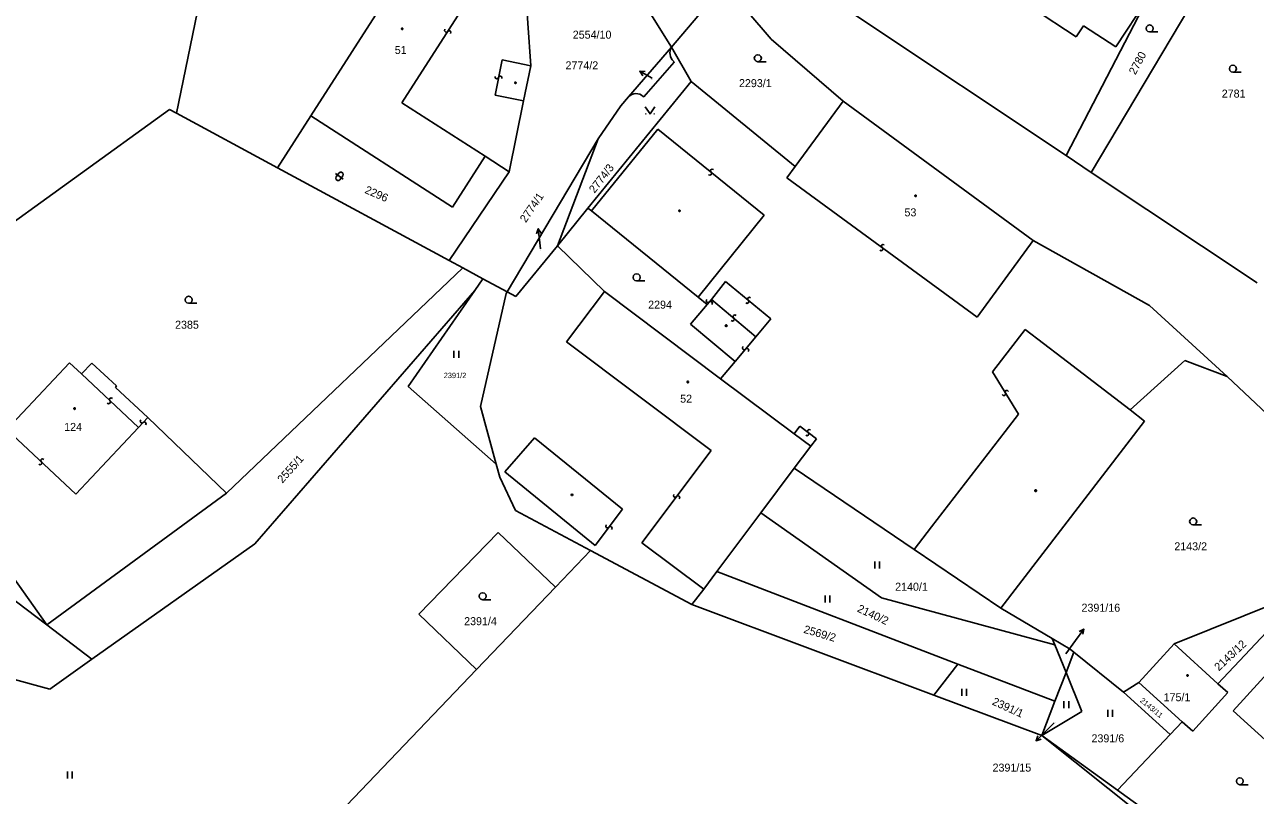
# Model space of a CAD drawing. Extents: x -747792 to -745414, y -1093712 to -1091463.
# Drawn here: x -746752.4 to -746621.6, y -1093197 to -1093115.1 of the extents above; entities that cross this region are included whole.
import ezdxf

# ---------------------------------------------------------------- set-up
doc = ezdxf.new("R2010")
doc.units = 0
for name, color, linetype in [('Pracovní_bod JDTM STC_VC', 7, 'Continuous'), ('Pracovní_bod JDTM STC_VC - výška', 7, 'Continuous'), ('Pracovní_bod JDTM STC_VC - číslo', 7, 'Continuous'), ('Pracovní_bod NN - výška', 7, 'Continuous'), ('Pracovní_bod polohopisu', 7, 'Continuous'), ('Pracovní_bod polohopisu - výška', 7, 'Continuous')]:
    doc.layers.add(name, color=color, linetype=linetype)

msp = doc.modelspace()

# ---------------------------------------------------------------- linework, layer by layer
at = {"layer": 'Pracovní_bod JDTM STC_VC - výška'}
for points in [[(-746712.23, -1093115.44), (-746712.18, -1093115.45), (-746712.16, -1093115.49), (-746712.15, -1093115.52), (-746712.16, -1093115.56), (-746712.2, -1093115.6), (-746712.23, -1093115.6), (-746712.27, -1093115.59), (-746712.3, -1093115.56), (-746712.32, -1093115.52), (-746712.3, -1093115.48), (-746712.26, -1093115.44)], [(-746700.16, -1093121.19), (-746700.11, -1093121.26), (-746700.16, -1093121.33), (-746700.24, -1093121.33), (-746700.29, -1093121.26), (-746700.24, -1093121.19)], [(-746657.7, -1093133.19), (-746657.65, -1093133.2), (-746657.62, -1093133.24), (-746657.61, -1093133.27), (-746657.62, -1093133.31), (-746657.67, -1093133.35), (-746657.7, -1093133.35), (-746657.74, -1093133.34), (-746657.77, -1093133.31), (-746657.78, -1093133.27), (-746657.77, -1093133.23), (-746657.73, -1093133.19)], [(-746682.75, -1093134.78), (-746682.7, -1093134.85), (-746682.75, -1093134.93), (-746682.83, -1093134.93), (-746682.88, -1093134.85), (-746682.83, -1093134.78)], [(-746677.77, -1093146.99), (-746677.73, -1093147.06), (-746677.77, -1093147.14), (-746677.86, -1093147.14), (-746677.91, -1093147.06), (-746677.86, -1093146.99)], [(-746681.89, -1093152.98), (-746681.84, -1093152.99), (-746681.82, -1093153.03), (-746681.8, -1093153.06), (-746681.82, -1093153.1), (-746681.85, -1093153.14), (-746681.89, -1093153.15), (-746681.94, -1093153.13), (-746681.97, -1093153.1), (-746681.98, -1093153.06), (-746681.97, -1093153.02), (-746681.93, -1093152.98)], [(-746747.05, -1093155.79), (-746747, -1093155.8), (-746746.98, -1093155.85), (-746746.97, -1093155.88), (-746746.98, -1093155.92), (-746747.02, -1093155.96), (-746747.05, -1093155.96), (-746747.09, -1093155.95), (-746747.12, -1093155.92), (-746747.14, -1093155.88), (-746747.12, -1093155.83), (-746747.08, -1093155.8)], [(-746694.16, -1093164.97), (-746694.11, -1093165.04), (-746694.16, -1093165.11), (-746694.24, -1093165.11), (-746694.29, -1093165.04), (-746694.24, -1093164.97)], [(-746644.9, -1093164.52), (-746644.85, -1093164.59), (-746644.9, -1093164.67), (-746644.98, -1093164.67), (-746645.03, -1093164.59), (-746644.98, -1093164.52)], [(-746628.81, -1093184.15), (-746628.76, -1093184.16), (-746628.74, -1093184.2), (-746628.73, -1093184.23), (-746628.74, -1093184.27), (-746628.78, -1093184.31), (-746628.81, -1093184.31), (-746628.85, -1093184.3), (-746628.89, -1093184.27), (-746628.9, -1093184.23), (-746628.89, -1093184.19), (-746628.84, -1093184.15)]]:
    msp.add_lwpolyline(points, close=True, dxfattribs=at)
at = {"layer": 'Pracovní_bod JDTM STC_VC - číslo'}
for points in [[(-746632.83, -1093115.86), (-746633.02, -1093115.81), (-746633.16, -1093115.67), (-746633.2, -1093115.49), (-746633.16, -1093115.3), (-746633.02, -1093115.16), (-746632.83, -1093115.11), (-746632.64, -1093115.16), (-746632.5, -1093115.3), (-746632.45, -1093115.49), (-746632.5, -1093115.67), (-746632.64, -1093115.81), (-746632.83, -1093115.86), (-746631.95, -1093115.86)], [(-746674.46, -1093119.02), (-746674.65, -1093118.97), (-746674.78, -1093118.83), (-746674.83, -1093118.65), (-746674.78, -1093118.46), (-746674.65, -1093118.32), (-746674.46, -1093118.27), (-746674.27, -1093118.32), (-746674.14, -1093118.46), (-746674.08, -1093118.65), (-746674.14, -1093118.83), (-746674.27, -1093118.97), (-746674.46, -1093119.02), (-746673.58, -1093119.02)], [(-746623.99, -1093120.13), (-746624.18, -1093120.08), (-746624.32, -1093119.94), (-746624.36, -1093119.76), (-746624.32, -1093119.57), (-746624.18, -1093119.43), (-746623.99, -1093119.38), (-746623.8, -1093119.43), (-746623.67, -1093119.57), (-746623.61, -1093119.76), (-746623.67, -1093119.94), (-746623.8, -1093120.08), (-746623.99, -1093120.13), (-746623.11, -1093120.13)], [(-746686.41, -1093123.82), (-746685.91, -1093124.57), (-746685.41, -1093123.82)], [(-746686.39, -1093124.57), (-746686.33, -1093124.57)], [(-746685.49, -1093124.57), (-746685.44, -1093124.57)], [(-746719.31, -1093130.91), (-746718.8, -1093131.29), (-746718.5, -1093131.5)], [(-746687.34, -1093142.31), (-746687.53, -1093142.26), (-746687.67, -1093142.12), (-746687.71, -1093141.94), (-746687.67, -1093141.75), (-746687.53, -1093141.61), (-746687.34, -1093141.56), (-746687.15, -1093141.61), (-746687.01, -1093141.75), (-746686.96, -1093141.94), (-746687.01, -1093142.12), (-746687.15, -1093142.26), (-746687.34, -1093142.31), (-746686.46, -1093142.31)], [(-746734.93, -1093144.69), (-746735.12, -1093144.64), (-746735.26, -1093144.5), (-746735.31, -1093144.31), (-746735.26, -1093144.13), (-746735.12, -1093143.99), (-746734.93, -1093143.94), (-746734.74, -1093143.99), (-746734.6, -1093144.13), (-746734.56, -1093144.31), (-746734.6, -1093144.5), (-746734.74, -1093144.64), (-746734.93, -1093144.69), (-746734.06, -1093144.69)], [(-746706.74, -1093149.75), (-746706.74, -1093150.5)], [(-746706.24, -1093150.5), (-746706.24, -1093149.75)], [(-746628.21, -1093168.24), (-746628.4, -1093168.19), (-746628.53, -1093168.05), (-746628.58, -1093167.86), (-746628.53, -1093167.68), (-746628.4, -1093167.54), (-746628.21, -1093167.49), (-746628.02, -1093167.54), (-746627.89, -1093167.68), (-746627.83, -1093167.86), (-746627.89, -1093168.05), (-746628.02, -1093168.19), (-746628.21, -1093168.24), (-746627.33, -1093168.24)], [(-746662.04, -1093172.13), (-746662.04, -1093172.88)], [(-746661.54, -1093172.88), (-746661.54, -1093172.13)], [(-746703.69, -1093176.19), (-746703.88, -1093176.14), (-746704.01, -1093176), (-746704.07, -1093175.81), (-746704.01, -1093175.63), (-746703.88, -1093175.49), (-746703.69, -1093175.44), (-746703.5, -1093175.49), (-746703.36, -1093175.63), (-746703.32, -1093175.81), (-746703.36, -1093176), (-746703.5, -1093176.14), (-746703.69, -1093176.19), (-746702.82, -1093176.19)], [(-746667.32, -1093175.73), (-746667.32, -1093176.48)], [(-746666.82, -1093176.48), (-746666.82, -1093175.73)], [(-746652.78, -1093185.66), (-746652.78, -1093186.41)], [(-746652.28, -1093186.41), (-746652.28, -1093185.66)], [(-746641.93, -1093186.96), (-746641.93, -1093187.71)], [(-746641.43, -1093187.71), (-746641.43, -1093186.96)], [(-746637.29, -1093187.89), (-746637.29, -1093188.64)], [(-746636.79, -1093188.64), (-746636.79, -1093187.89)], [(-746747.8, -1093194.44), (-746747.8, -1093195.19)], [(-746747.3, -1093195.19), (-746747.3, -1093194.44)], [(-746623.25, -1093195.85), (-746623.44, -1093195.8), (-746623.58, -1093195.66), (-746623.62, -1093195.48), (-746623.58, -1093195.29), (-746623.44, -1093195.15), (-746623.25, -1093195.1), (-746623.06, -1093195.15), (-746622.93, -1093195.29), (-746622.88, -1093195.48), (-746622.93, -1093195.66), (-746623.06, -1093195.8), (-746623.25, -1093195.85), (-746622.38, -1093195.85)]]:
    msp.add_lwpolyline(points, dxfattribs=at)
msp.add_lwpolyline([(-746718.96, -1093130.86), (-746718.83, -1093130.77), (-746718.68, -1093130.77), (-746718.56, -1093130.86), (-746718.51, -1093131.01), (-746718.55, -1093131.15), (-746718.85, -1093131.56), (-746718.97, -1093131.65), (-746719.13, -1093131.65), (-746719.25, -1093131.55), (-746719.3, -1093131.41), (-746719.25, -1093131.26)], close=True, dxfattribs=at)
at = {"layer": 'Pracovní_bod NN - výška'}
for points in [[(-746731.29, -1093100.55), (-746736.23, -1093124.49)], [(-746708.76, -1093104.21), (-746721.96, -1093124.78)], [(-746624.9, -1093107.01), (-746639.04, -1093130.78)], [(-746699.2, -1093110.35), (-746698.59, -1093119.45)], [(-746676.87, -1093112.49), (-746675.62, -1093113.6), (-746673.04, -1093116.62)], [(-746641.71, -1093129), (-746633.07, -1093112.31)], [(-746633.07, -1093112.31), (-746636.44, -1093117.45)], [(-746683.64, -1093117.48), (-746685.84, -1093113.95)], [(-746683.64, -1093117.48), (-746679.61, -1093112.76)], [(-746645.26, -1093113.33), (-746640.63, -1093116.36)], [(-746641.71, -1093129), (-746664.05, -1093114.11)], [(-746639.87, -1093115.2), (-746640.63, -1093116.36)], [(-746636.44, -1093117.45), (-746639.87, -1093115.2)], [(-746673.04, -1093116.62), (-746665.39, -1093123.22)], [(-746688.2, -1093122.76), (-746683.64, -1093117.48)], [(-746681.53, -1093121.11), (-746683.64, -1093117.48)], [(-746686.63, -1093122.7), (-746686.57, -1093122.75), (-746683.33, -1093119.05), (-746683.41, -1093118.98)], [(-746698.59, -1093119.45), (-746699.34, -1093123.17)], [(-746681.53, -1093121.11), (-746692.51, -1093134.57)], [(-746670.48, -1093130.15), (-746681.53, -1093121.11)], [(-746688.2, -1093122.76), (-746689, -1093123.69)], [(-746736.95, -1093124.11), (-746757.19, -1093138.7)], [(-746736.95, -1093124.11), (-746736.23, -1093124.49)], [(-746699.34, -1093123.17), (-746700.86, -1093130.72)], [(-746689, -1093123.69), (-746691.42, -1093127.21)], [(-746665.39, -1093123.22), (-746670.48, -1093130.15)], [(-746665.39, -1093123.22), (-746645.19, -1093138.03)], [(-746725.5, -1093130.29), (-746736.23, -1093124.49)], [(-746721.96, -1093124.78), (-746725.5, -1093130.29)], [(-746721.96, -1093124.78), (-746706.88, -1093134.46)], [(-746701.08, -1093143.48), (-746691.42, -1093127.21)], [(-746695.73, -1093138.59), (-746691.42, -1093127.21)], [(-746706.88, -1093134.46), (-746703.42, -1093129.07)], [(-746703.42, -1093129.07), (-746700.86, -1093130.72)], [(-746641.71, -1093129), (-746639.04, -1093130.78)], [(-746725.5, -1093130.29), (-746707.26, -1093140.14)], [(-746700.86, -1093130.72), (-746707.26, -1093140.14)], [(-746639.04, -1093130.78), (-746621.42, -1093142.52)], [(-746692.51, -1093134.57), (-746695.73, -1093138.59)], [(-746692.14, -1093134.87), (-746692.51, -1093134.57)], [(-746692.14, -1093134.87), (-746680.81, -1093144.04)], [(-746695.73, -1093138.59), (-746700.16, -1093143.98)], [(-746695.73, -1093138.59), (-746690.76, -1093143.45)], [(-746645.19, -1093138.03), (-746632.83, -1093144.93)], [(-746705.79, -1093140.93), (-746707.26, -1093140.14)], [(-746799.41, -1093141.43), (-746750.01, -1093178.87)], [(-746705.79, -1093140.93), (-746730.9, -1093164.85)], [(-746705.79, -1093140.93), (-746703.67, -1093142.08)], [(-746704.53, -1093143.32), (-746703.67, -1093142.08)], [(-746703.67, -1093142.08), (-746701.08, -1093143.48)], [(-746727.91, -1093170.24), (-746704.53, -1093143.32)], [(-746704.53, -1093143.32), (-746711.61, -1093153.53)], [(-746701.19, -1093143.66), (-746703.92, -1093155.65)], [(-746701.19, -1093143.66), (-746701.08, -1093143.48)], [(-746701.08, -1093143.48), (-746700.16, -1093143.98)], [(-746690.76, -1093143.45), (-746678.41, -1093152.7)], [(-746680.81, -1093144.04), (-746679.85, -1093144.82)], [(-746679.85, -1093144.82), (-746681.6, -1093146.9)], [(-746624.59, -1093152.46), (-746632.83, -1093144.93)], [(-746681.6, -1093146.9), (-746676.87, -1093150.87)], [(-746754.24, -1093158.09), (-746747.58, -1093151.01)], [(-746747.58, -1093151.01), (-746746.31, -1093152.2)], [(-746746.31, -1093152.2), (-746745.22, -1093151.04)], [(-746742.58, -1093153.47), (-746745.22, -1093151.04)], [(-746676.87, -1093150.87), (-746678.41, -1093152.7)], [(-746634.91, -1093156), (-746629.11, -1093150.78)], [(-746629.11, -1093150.78), (-746624.59, -1093152.46)], [(-746678.41, -1093152.7), (-746670.59, -1093158.56)], [(-746608.82, -1093167.31), (-746624.59, -1093152.46)], [(-746742.71, -1093153.62), (-746742.58, -1093153.47)], [(-746739.26, -1093156.81), (-746742.71, -1093153.62)], [(-746711.61, -1093153.53), (-746702.25, -1093161.78)], [(-746703.92, -1093155.65), (-746702.25, -1093161.78)], [(-746739.26, -1093156.81), (-746730.9, -1093164.85)], [(-746633.36, -1093157.2), (-746634.91, -1093156)], [(-746633.36, -1093157.2), (-746648.65, -1093177.1)], [(-746670.59, -1093158.56), (-746668.83, -1093159.88)], [(-746670.59, -1093162.22), (-746668.83, -1093159.88)], [(-746702.25, -1093161.78), (-746701.87, -1093163.17)], [(-746670.59, -1093162.22), (-746674.14, -1093166.96)], [(-746657.85, -1093170.86), (-746670.59, -1093162.22)], [(-746701.87, -1093163.17), (-746700.22, -1093166.72)], [(-746750.01, -1093178.87), (-746730.9, -1093164.85)], [(-746692.24, -1093170.95), (-746700.22, -1093166.72)], [(-746674.14, -1093166.96), (-746678.8, -1093173.18)], [(-746674.14, -1093166.96), (-746661.33, -1093176)], [(-746745.21, -1093182.5), (-746727.91, -1093170.24)], [(-746710.48, -1093177.73), (-746702.04, -1093169.05)], [(-746702.04, -1093169.05), (-746695.97, -1093174.85)], [(-746756.02, -1093170.38), (-746750.01, -1093178.87)], [(-746695.97, -1093174.85), (-746692.24, -1093170.95)], [(-746692.24, -1093170.95), (-746681.46, -1093176.68)], [(-746657.85, -1093170.86), (-746648.65, -1093177.1)], [(-746678.8, -1093173.18), (-746680.21, -1093175.06)], [(-746678.8, -1093173.18), (-746653.21, -1093183.03)], [(-746695.97, -1093174.85), (-746704.33, -1093183.6)], [(-746680.21, -1093175.06), (-746681.46, -1093176.68)], [(-746616.43, -1093175.39), (-746625.58, -1093185.11)], [(-746655.75, -1093186.33), (-746681.46, -1093176.68)], [(-746661.33, -1093176), (-746642.91, -1093180.99)], [(-746630.23, -1093180.88), (-746619.04, -1093176.37)], [(-746704.33, -1093183.6), (-746710.48, -1093177.73)], [(-746648.65, -1093177.1), (-746643.19, -1093180.31)], [(-746750.01, -1093178.87), (-746745.21, -1093182.5)], [(-746643.19, -1093180.31), (-746641.27, -1093181.44)], [(-746642.91, -1093180.99), (-746643.19, -1093180.31)], [(-746617.05, -1093180.4), (-746623.94, -1093188.01)], [(-746641.71, -1093183.92), (-746642.91, -1093180.99)], [(-746640.88, -1093181.75), (-746641.71, -1093183.92)], [(-746641.27, -1093181.44), (-746640.88, -1093181.75)], [(-746640.88, -1093181.75), (-746635.6, -1093186.02)], [(-746633.98, -1093184.98), (-746630.23, -1093180.88)], [(-746630.23, -1093180.88), (-746625.58, -1093185.11)], [(-746759.18, -1093183.11), (-746749.69, -1093185.68)], [(-746749.69, -1093185.68), (-746745.21, -1093182.5)], [(-746653.21, -1093183.03), (-746655.75, -1093186.33)], [(-746642.89, -1093186.97), (-746653.21, -1093183.03)], [(-746744.22, -1093225.34), (-746704.33, -1093183.6)], [(-746641.71, -1093183.92), (-746642.89, -1093186.97)], [(-746641.71, -1093183.92), (-746640.02, -1093188.06)], [(-746635.6, -1093186.02), (-746633.98, -1093184.98)], [(-746633.98, -1093184.98), (-746629.38, -1093189.15)], [(-746625.58, -1093185.11), (-746624.53, -1093186.06)], [(-746644.3, -1093190.63), (-746655.75, -1093186.33)], [(-746642.89, -1093186.97), (-746644.3, -1093190.63)], [(-746630.66, -1093190.5), (-746635.6, -1093186.02)], [(-746624.53, -1093186.06), (-746628.26, -1093190.17)], [(-746644.3, -1093190.63), (-746640.02, -1093188.06)], [(-746623.94, -1093188.01), (-746614.06, -1093196.96)], [(-746629.38, -1093189.15), (-746630.66, -1093190.5)], [(-746628.26, -1093190.17), (-746629.38, -1093189.15)], [(-746623.42, -1093207.26), (-746644.3, -1093190.63)], [(-746636.24, -1093196.43), (-746644.3, -1093190.63)], [(-746630.66, -1093190.5), (-746636.24, -1093196.43)], [(-746636.24, -1093196.43), (-746619.07, -1093208.84)]]:
    msp.add_lwpolyline(points, dxfattribs=at)
for centre, radius, start, end in [((-746682.55, -1093118.08), 1.24, 151.1429, 226.292), ((-746687.38, -1093123.53), 1.12, 47.8191, 136.5581)]:
    msp.add_arc(centre, radius, start, end, dxfattribs=at)
at = {"layer": 'Pracovní_bod polohopisu'}
for points in [[(-746712.28, -1093123.38), (-746702.53, -1093108.21)], [(-746707.71, -1093115.57), (-746707.75, -1093115.72), (-746707.65, -1093115.86), (-746707.5, -1093115.87), (-746707.3, -1093115.72), (-746707.15, -1093115.74), (-746707.06, -1093115.88), (-746707.1, -1093116.02)], [(-746701.63, -1093118.83), (-746702.38, -1093122.56)], [(-746698.59, -1093119.45), (-746701.63, -1093118.83)], [(-746701.64, -1093120.79), (-746701.66, -1093120.64), (-746701.8, -1093120.55), (-746701.95, -1093120.59), (-746702.08, -1093120.81), (-746702.23, -1093120.84), (-746702.36, -1093120.74), (-746702.37, -1093120.6)], [(-746702.38, -1093122.56), (-746699.34, -1093123.17)], [(-746703.42, -1093129.07), (-746712.28, -1093123.38)], [(-746692.14, -1093134.87), (-746685.09, -1093126.17)], [(-746685.09, -1093126.17), (-746673.77, -1093135.34)], [(-746679.17, -1093130.48), (-746679.32, -1093130.42), (-746679.47, -1093130.51), (-746679.5, -1093130.66), (-746679.36, -1093130.87), (-746679.41, -1093131.02), (-746679.55, -1093131.09), (-746679.69, -1093131.03)], [(-746670.48, -1093130.15), (-746671.36, -1093131.36)], [(-746671.36, -1093131.36), (-746651.16, -1093146.17)], [(-746673.77, -1093135.34), (-746680.81, -1093144.04)], [(-746661.02, -1093138.48), (-746661.17, -1093138.43), (-746661.31, -1093138.52), (-746661.33, -1093138.67), (-746661.19, -1093138.88), (-746661.22, -1093139.03), (-746661.37, -1093139.1), (-746661.5, -1093139.05)], [(-746651.16, -1093146.17), (-746645.19, -1093138.03)], [(-746679.39, -1093144.27), (-746677.88, -1093142.39)], [(-746673.07, -1093146.35), (-746677.88, -1093142.39)], [(-746694.77, -1093148.8), (-746690.76, -1093143.45)], [(-746675.73, -1093144.64), (-746675.59, -1093144.7), (-746675.44, -1093144.62), (-746675.41, -1093144.47), (-746675.54, -1093144.25), (-746675.5, -1093144.11), (-746675.35, -1093144.04), (-746675.22, -1093144.1)], [(-746679.35, -1093144.8), (-746679.29, -1093144.66), (-746679.37, -1093144.51), (-746679.52, -1093144.48), (-746679.74, -1093144.61), (-746679.88, -1093144.56), (-746679.95, -1093144.42), (-746679.89, -1093144.29)], [(-746679.39, -1093144.27), (-746679.85, -1093144.82)], [(-746674.66, -1093148.24), (-746679.39, -1093144.27)], [(-746677.29, -1093146.53), (-746677.14, -1093146.58), (-746676.99, -1093146.5), (-746676.96, -1093146.36), (-746677.09, -1093146.14), (-746677.04, -1093145.99), (-746676.9, -1093145.92), (-746676.76, -1093145.98)], [(-746674.66, -1093148.24), (-746673.07, -1093146.35)], [(-746646.05, -1093147.46), (-746649.54, -1093151.96)], [(-746642.16, -1093150.44), (-746646.05, -1093147.46)], [(-746679.41, -1093160.32), (-746694.77, -1093148.8)], [(-746676.87, -1093150.87), (-746674.66, -1093148.24)], [(-746676.04, -1093149.29), (-746676.09, -1093149.44), (-746676.01, -1093149.59), (-746675.87, -1093149.62), (-746675.65, -1093149.49), (-746675.5, -1093149.54), (-746675.43, -1093149.68), (-746675.49, -1093149.82)], [(-746634.91, -1093156), (-746642.16, -1093150.44)], [(-746746.31, -1093152.2), (-746740.27, -1093157.89)], [(-746649.54, -1093151.96), (-746646.77, -1093156.48)], [(-746647.82, -1093154.05), (-746647.94, -1093153.94), (-746648.11, -1093153.97), (-746648.19, -1093154.1), (-746648.13, -1093154.35), (-746648.22, -1093154.48), (-746648.38, -1093154.49), (-746648.49, -1093154.39)], [(-746743.01, -1093154.79), (-746743.16, -1093154.72), (-746743.31, -1093154.79), (-746743.35, -1093154.94), (-746743.23, -1093155.17), (-746743.29, -1093155.31), (-746743.44, -1093155.37), (-746743.57, -1093155.3)], [(-746740.27, -1093157.89), (-746739.26, -1093156.81)], [(-746740.02, -1093157.08), (-746740.09, -1093157.22), (-746740.02, -1093157.37), (-746739.87, -1093157.41), (-746739.64, -1093157.29), (-746739.5, -1093157.34), (-746739.44, -1093157.49), (-746739.51, -1093157.62)], [(-746648.17, -1093158.31), (-746646.77, -1093156.48)], [(-746746.93, -1093164.97), (-746754.24, -1093158.09)], [(-746746.93, -1093164.97), (-746740.27, -1093157.89)], [(-746670.59, -1093158.56), (-746669.99, -1093157.76)], [(-746669.99, -1093157.76), (-746668.23, -1093159.08)], [(-746668.86, -1093158.14), (-746669.01, -1093158.09), (-746669.16, -1093158.17), (-746669.18, -1093158.32), (-746669.04, -1093158.54), (-746669.08, -1093158.68), (-746669.22, -1093158.76), (-746669.36, -1093158.7)], [(-746655.99, -1093168.44), (-746648.17, -1093158.31)], [(-746698.17, -1093158.98), (-746701.35, -1093162.58)], [(-746688.83, -1093166.55), (-746698.17, -1093158.98)], [(-746668.83, -1093159.88), (-746668.23, -1093159.08)], [(-746686.77, -1093170.14), (-746679.41, -1093160.32)], [(-746750.86, -1093161.79), (-746750.72, -1093161.85), (-746750.57, -1093161.78), (-746750.53, -1093161.63), (-746750.64, -1093161.41), (-746750.59, -1093161.26), (-746750.44, -1093161.21), (-746750.31, -1093161.27)], [(-746691.73, -1093170.42), (-746701.35, -1093162.58)], [(-746683.38, -1093164.99), (-746683.43, -1093165.14), (-746683.34, -1093165.28), (-746683.19, -1093165.3), (-746682.98, -1093165.16), (-746682.83, -1093165.2), (-746682.75, -1093165.34), (-746682.8, -1093165.47)], [(-746691.73, -1093170.42), (-746688.83, -1093166.55)], [(-746690.57, -1093168.24), (-746690.62, -1093168.39), (-746690.53, -1093168.53), (-746690.38, -1093168.56), (-746690.17, -1093168.41), (-746690.02, -1093168.45), (-746689.94, -1093168.59), (-746689.99, -1093168.73)], [(-746655.99, -1093168.44), (-746657.85, -1093170.86)], [(-746686.77, -1093170.14), (-746680.21, -1093175.06)]]:
    msp.add_lwpolyline(points, dxfattribs=at)
at = {"layer": 'Pracovní_bod polohopisu - výška'}
for points in [[(-746687, -1093120.04), (-746685.69, -1093120.78)], [(-746686.68, -1093120.51), (-746687, -1093120.04), (-746686.44, -1093120.07)], [(-746697.98, -1093137.29), (-746697.79, -1093136.76), (-746697.48, -1093137.23)], [(-746697.79, -1093136.76), (-746697.61, -1093138.25)], [(-746697.54, -1093138.9), (-746697.61, -1093138.25)], [(-746639.83, -1093179.3), (-746640.7, -1093180.52)], [(-746640.32, -1093179.56), (-746639.83, -1093179.3), (-746639.92, -1093179.85)], [(-746641.72, -1093181.95), (-746640.7, -1093180.52)], [(-746642.96, -1093189.26), (-746643.83, -1093190.12)], [(-746644.9, -1093191.17), (-746643.83, -1093190.12)], [(-746644.37, -1093191), (-746644.9, -1093191.17), (-746644.72, -1093190.64)]]:
    msp.add_lwpolyline(points, dxfattribs=at)

# ---------------------------------------------------------------- texts
at = {"layer": 'Pracovní_bod JDTM STC_VC'}
for s, height, p in [('2554/10', 0.85, (-746694.12, -1093116.57)), ('51', 0.85, (-746713.03, -1093118.2)), ('2293/1', 0.85, (-746676.46, -1093121.72)), ('2781', 0.85, (-746625.17, -1093122.83)), ('53', 0.85, (-746658.88, -1093135.45)), ('2294', 0.85, (-746686.11, -1093145.26)), ('2385', 0.85, (-746736.37, -1093147.39)), ('2391/2', 0.57, (-746707.83, -1093152.64)), ('52', 0.85, (-746682.71, -1093155.25)), ('124', 0.85, (-746748.15, -1093158.25)), ('2143/2', 0.85, (-746630.21, -1093170.94)), ('2140/1', 0.85, (-746659.87, -1093175.23)), ('2391/4', 0.85, (-746705.66, -1093178.89)), ('2391/16', 0.05, (-746641.85, -1093181.95)), ('175/1', 0.85, (-746631.35, -1093186.97)), ('2391/15', 0.05, (-746643.09, -1093189.26)), ('2391/6', 0.85, (-746639.01, -1093191.34))]:
    msp.add_text(s, height=height, dxfattribs=at).set_placement(p)
for s, height, rotation, p in [('2780', 0.85, 61.7649, (-746634.35, -1093120.47)), ('2774/2', 0.05, 57.4677, (-746685.74, -1093120.99)), ('2774/3', 0.85, 52.4256, (-746691.8, -1093133.05)), ('2296', 0.85, 336.4981, (-746716.29, -1093132.94)), ('2774/1', 0.05, 57.4677, (-746697.59, -1093139.1)), ('2555/1', 0.85, 48.0712, (-746724.96, -1093163.86)), ('2140/2', 0.85, 335.0084, (-746663.97, -1093177.42)), ('2569/2', 0.85, 343.6601, (-746669.65, -1093179.69)), ('2143/12', 0.85, 43.0864, (-746625.48, -1093183.81)), ('2391/1', 0.85, 335.5814, (-746649.64, -1093187.3)), ('2143/11', 0.57, 320.5126, (-746633.91, -1093186.99))]:
    msp.add_text(s, height=height, rotation=rotation, dxfattribs=at).set_placement(p)
at = {"layer": 'Pracovní_bod polohopisu - výška'}
for s, p in [('2774/2', (-746694.89, -1093119.83)), ('2391/16', (-746640.07, -1093177.46)), ('2391/15', (-746649.52, -1093194.45))]:
    msp.add_text(s, height=0.85, dxfattribs=at).set_placement(p)
msp.add_text('2774/1', height=0.85, rotation=55.6915, dxfattribs=at).set_placement((-746699.11, -1093136.18))

doc.saveas('drawing.dxf')
